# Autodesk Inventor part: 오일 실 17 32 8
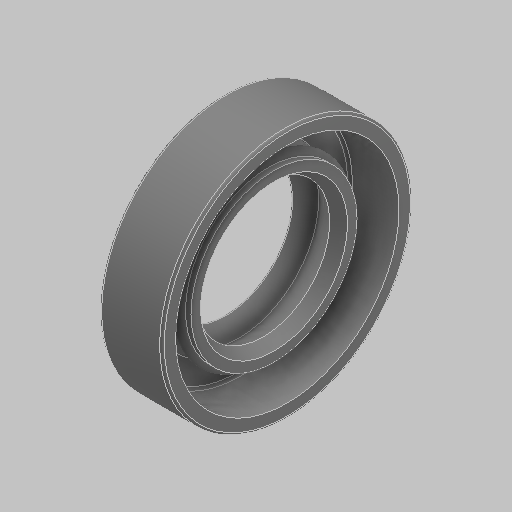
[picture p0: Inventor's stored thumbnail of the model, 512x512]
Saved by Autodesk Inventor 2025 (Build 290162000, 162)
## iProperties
Created: 2024-08
Part Number: 오일 실 17 32 8
Material: 고무
Description: 오일-실
Document SubType Name: Modeling
Designer: 현기
Density: 0.93 g/cm^3
Appearance: 기본값
Author: jhkim
Sending System: Autodesk Inventor 2025
Preprocessor: ST-DEVELOPER v20
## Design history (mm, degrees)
feature "Solid1"
node "솔리드1"
